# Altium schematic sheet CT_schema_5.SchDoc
size 289 x 230 mm
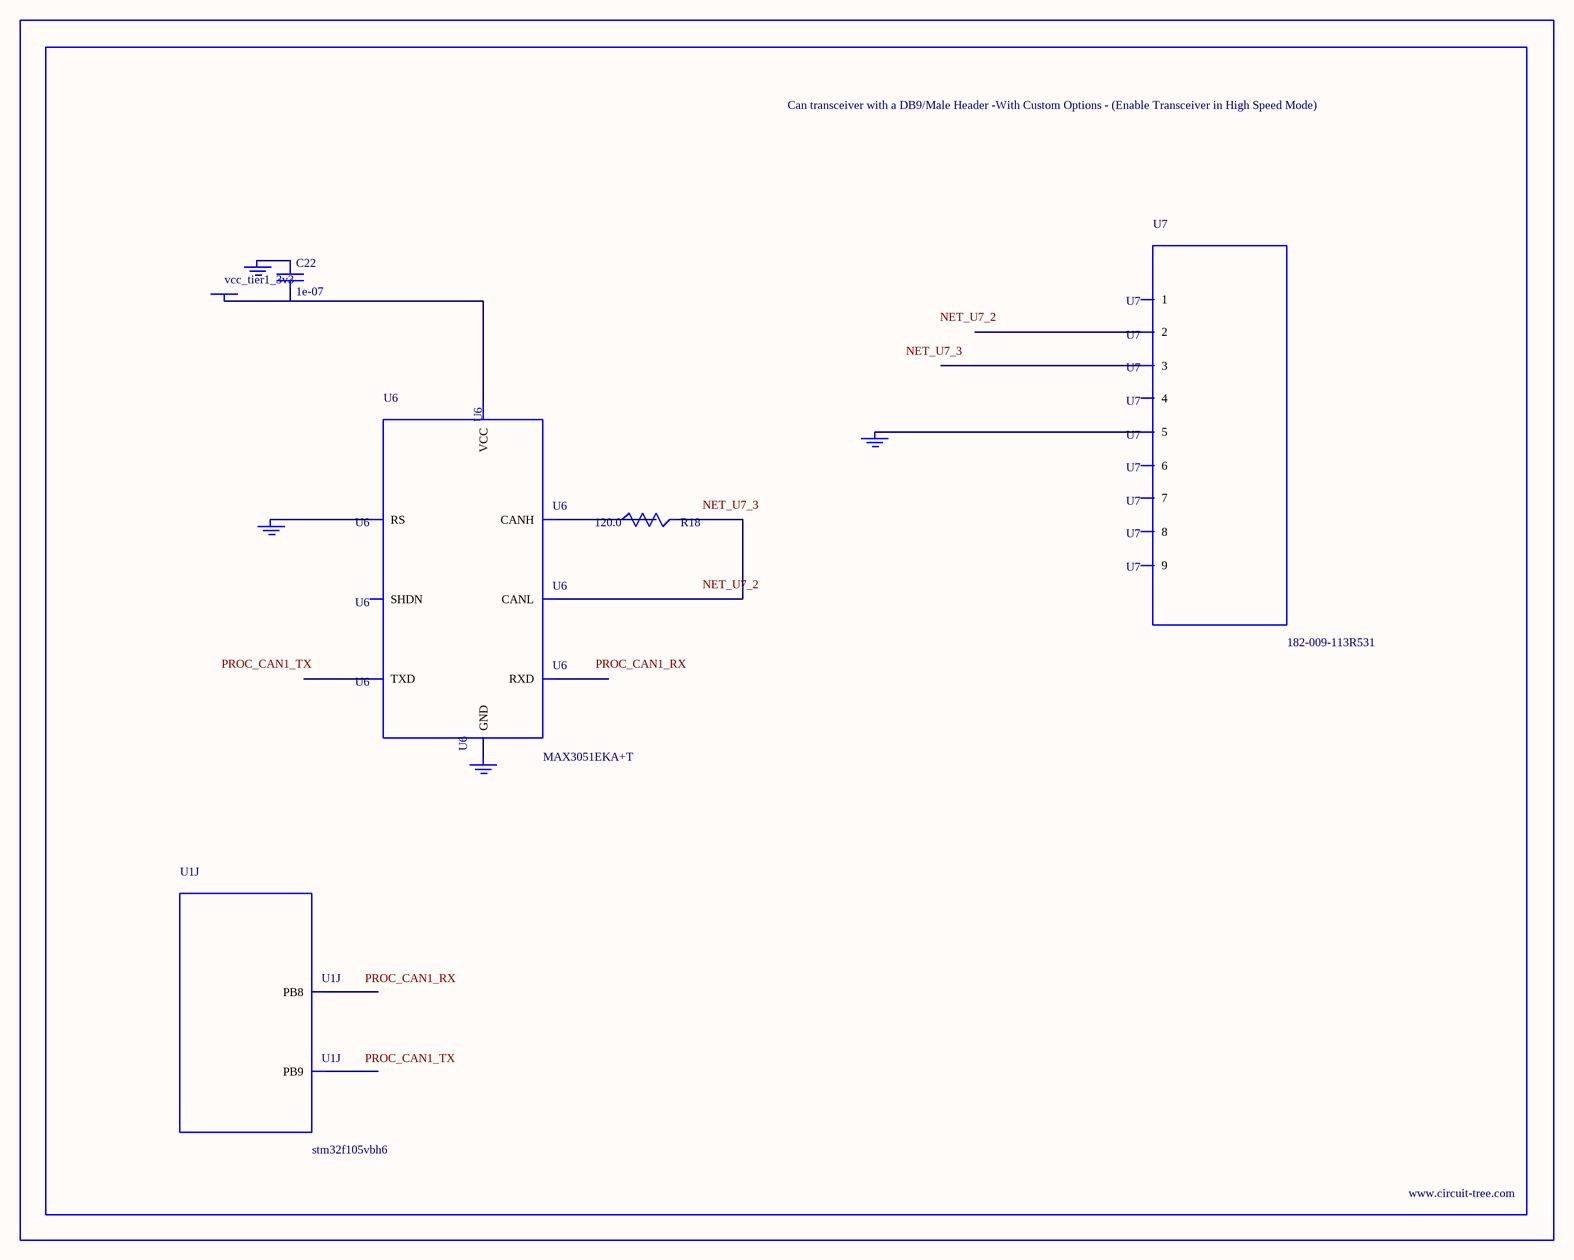
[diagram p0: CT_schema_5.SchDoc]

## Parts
BORDER4  (no value)
C22  1e-07  [C0402]
GND_INSTANCE_4_0  (no value)
GND_INSTANCE_4_1  (no value)
GND_INSTANCE_4_2  (no value)
GND_INSTANCE_4_3  (no value)
POWER_INSTANCE_4_0  vcc_tier1_3v3
R18  120.0  [R0603]
U1  stm32f105vbh6  [LFBGA100]  (part J of 11)
U6  MAX3051EKA+T  [SOT-23-8]
U7  182-009-113R531  [182-009-MALE]

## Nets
NetC22_1: C22.1 GND_INSTANCE_4_0.0(GND)
NetC22_2: C22.2 POWER_INSTANCE_4_0.0(PWR) U6.3(VCC)
NetGND_INSTANCE_4_1_0: GND_INSTANCE_4_1.0(GND) U6.8(RS)
NetGND_INSTANCE_4_2_0: GND_INSTANCE_4_2.0(GND) U6.2(GND)
NetGND_INSTANCE_4_3_0: GND_INSTANCE_4_3.0(GND) U7.5
NetR18_1: R18.1 U6.7(CANH)
NetR18_2: R18.2 U6.6(CANL)

Not connected (* = marked no-connect by the designer): U1 A4(PB9) B4(PB8); U6 1(TXD) 4(RXD) 5(SHDN); U7 1 2 3 4 6 7 8 9

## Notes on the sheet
- Labels drawn without touching a wire or pin: NET_U7_2, NET_U7_3, PROC_CAN1_RX, PROC_CAN1_TX

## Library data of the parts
BORDER4 = BORDER_PAGE4
C22 = C0402C104K3RACTU
GND_INSTANCE_4_0-GND_INSTANCE_4_3 = GND
POWER_INSTANCE_4_0 = PWR
R18 = RC0603JR-07120RL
